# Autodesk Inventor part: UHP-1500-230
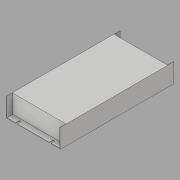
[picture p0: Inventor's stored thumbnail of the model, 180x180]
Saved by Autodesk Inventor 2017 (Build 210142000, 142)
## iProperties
Created: 2022-09
Part Number: UHP-1500-230
Material: Generic
Document SubType Name: Modeling
Designer: JTS
Density: 1 g/cm^3
Appearance: Default
Author: JTS
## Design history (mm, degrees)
sketch "Sketch1"
  geometry: L1 (-62.5, -21.9)-(62.5, -21.9); L2 (62.5, -21.9)-(62.5, 21.9); L3 (62.5, 21.9)-(-62.5, 21.9); L4 (-62.5, 21.9)-(-62.5, -21.9); L5 (-62.5, -21.9)-(62.5, 21.9); L6 (62.5, -21.9)-(-62.5, 21.9); 1 further point
  constraints: 12 end point, 2 horizontal, 2 midpoint, 2 vertical
  dimensions: "d0" = 125 distance of L1.start L1.end; "d1" = 43.8 distance of L3.end L1.start
extrude "Extrusion1" new body sketch "Sketch1" distance "d2" = 262; taper "d3" = 0 deg
sketch "Sketch2"
  geometry: L1 (125, -262)-(0, -262) reference; L2 (125, 0)-(0, 0) reference; L3 (23.5, -255.35)-(23.5, -6.65); L4 (23.5, -6.65)-(101.5, -6.65); L5 (101.5, -6.65)-(101.5, -255.35); L6 (23.5, -255.35)-(23.5, -262); L7 (23.5, -6.65)-(23.5, 0); L8 (23.5, -6.65)-(0, 0); L9 (101.5, -6.65)-(125, 0); L10 (99.25, -255.35)-(99.25, -262); L11 (103.75, -255.35)-(103.75, -262); L12 (21.25, -255.35)-(21.25, -262); L13 (25.75, -255.35)-(25.75, -262); L14 (25.75, -6.65)-(25.75, 0); L15 (21.25, -6.65)-(21.25, 0); L16 (103.75, -6.65)-(103.75, 0); L17 (99.25, -6.65)-(99.25, 0); A1 r 2.25 centre (23.5, -255.35) between (25.75, -255.35) and (21.25, -255.35); A2 r 2.25 centre (101.5, -255.35) between (103.75, -255.35) and (99.25, -255.35); A3 r 2.25 centre (101.5, -6.65) between (99.25, -6.65) and (103.75, -6.65); A4 r 2.25 centre (23.5, -6.65) between (21.25, -6.65) and (25.75, -6.65); 1 further point
  constraints: 30 end point, 12 vertical, 10 point on line, 8 point on circle, 8 tangent, 4 centre point, 3 equal length, 3 equal radius, 1 coincident, 1 horizontal
  dimensions: "d4" = 2.25 radius of A4; "d5" = 248.7 distance of L3.start L3.end; "d6" = 78 distance of L3.end L4.end
extrude "Extrusion2" cut sketch "Sketch2" stored distance "d7" = 290; taper "d8" = 0 deg
workplane "Work Plane1"
sketch "Sketch3"
  geometry: L1 (0, 262)-(0, 0) reference; L2 (125, 262)-(125, 0) reference; L3 (123.73, 0)-(123.73, 13.4); L4 (123.73, 13.4)-(1.27, 13.4); L5 (1.27, 13.4)-(1.27, 0); L6 (1.27, 0)-(123.73, 0); L7 (1.27, 0)-(0, 0); L8 (125, 0)-(123.73, 0); L9 (1.27, 248.6)-(123.73, 248.6); L10 (123.73, 248.6)-(123.73, 262); L11 (123.73, 262)-(1.27, 262); L12 (1.27, 262)-(1.27, 248.6); L13 (1.27, 262)-(0, 262); 1 further point
  constraints: 22 end point, 6 horizontal, 4 collinear, 2 vertical
  dimensions: "d9" = 1.27 distance of L5.end L1.end; "d14" = 235.2 distance between parallel lines of L4 L9
extrude "Extrusion3" cut sketch "Sketch3" stored distance "d12" = 290; taper "d13" = 0 deg
body "Solid1"
other parameters: "d11" = -1.27
